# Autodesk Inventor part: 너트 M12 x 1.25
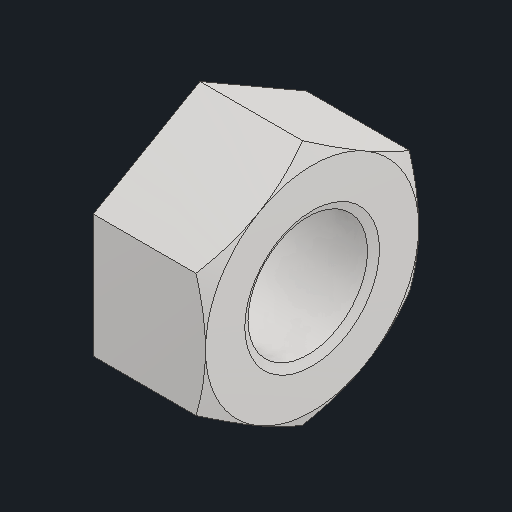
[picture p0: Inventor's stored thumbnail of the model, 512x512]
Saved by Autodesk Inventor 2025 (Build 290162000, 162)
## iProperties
Created: 2025-08
Part Number: 너트 M12 x 1.25
Material: 스테인리스강
Description: 6각 너트
Document SubType Name: Modeling
Designer: infra005
Density: 8.08 g/cm^3
Appearance: 기본값
Author: jhkim
Sending System: Autodesk Inventor 2026
Preprocessor: ST-DEVELOPER v20.1
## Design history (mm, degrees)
feature "Solid1"
node "솔리드1"
